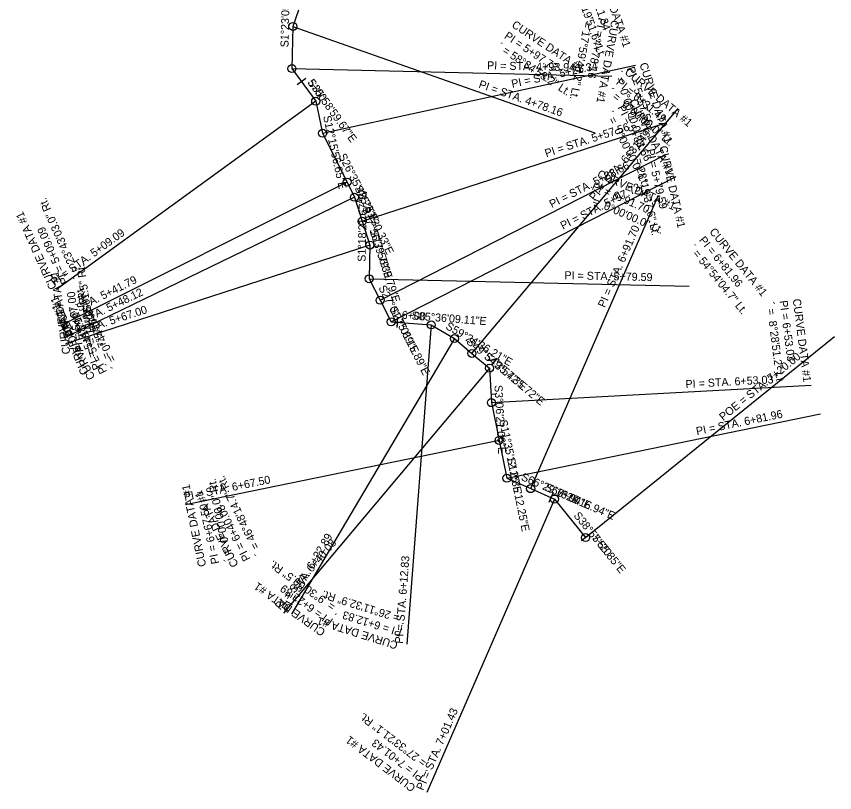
# Model space of a CAD drawing. Extents: x 1158784 to 1165006, y 610007 to 611539.
# Drawn here: x 1162821.2 to 1163128, y 610196.9 to 610487.8 of the extents above; entities that cross this region are included whole.
import ezdxf

# ---------------------------------------------------------------- set-up
doc = ezdxf.new("R2010")
doc.units = 0
for name, color, linetype in [('D_Roadway_Centerline', 7, 'Continuous'), ('D_Roadway_Centerline_Bearings', 7, 'Continuous'), ('D_Roadway_Centerline_CurveData', 7, 'Continuous'), ('D_Roadway_Centerline_Flags', 7, 'Continuous'), ('D_Roadway_Centerline_Text', 7, 'Continuous')]:
    doc.layers.add(name, color=color, linetype=linetype)

msp = doc.modelspace()

# ---------------------------------------------------------------- linework, layer by layer
at = {"layer": 'D_Roadway_Centerline'}
for p, q in [((1162927.06, 610490.12), (1162924.92, 610484.02)), ((1162924.92, 610484.02), (1162924.53, 610468.24)), ((1162924.53, 610468.24), (1162933.44, 610455.98)), ((1162933.44, 610455.98), (1162936.04, 610444.01)), ((1162936.04, 610444.01), (1162945.2, 610425.72)), ((1162945.2, 610425.72), (1162947.96, 610420.03)), ((1162947.96, 610420.03), (1162950.87, 610411.05)), ((1162950.87, 610411.05), (1162953.77, 610402.07)), ((1162953.77, 610402.07), (1162953.49, 610389.48)), ((1162953.49, 610389.48), (1162957.61, 610381.4)), ((1162957.61, 610381.4), (1162961.73, 610373.32)), ((1162961.73, 610373.32), (1162976.78, 610372.16)), ((1162976.78, 610372.16), (1162985.44, 610367.04)), ((1162985.44, 610367.04), (1162992.02, 610361.5)), ((1162992.02, 610361.5), (1162998.6, 610355.97)), ((1162998.6, 610355.97), (1162999.3, 610343.04)), ((1162999.3, 610343.04), (1163002.2, 610328.87)), ((1163002.2, 610328.87), (1163005.11, 610314.7)), ((1163005.11, 610314.7), (1163014.03, 610310.81)), ((1163014.03, 610310.81), (1163022.96, 610306.93)), ((1163022.96, 610306.93), (1163034.63, 610292.48))]:
    msp.add_line(p, q, dxfattribs=at)
at = {"layer": 'D_Roadway_Centerline_Flags'}
for points in [[(1162924.92, 610484.02), (1163038.11, 610444.19)], [(1162936.04, 610444.01), (1163053.3, 610469.5)], [(1162924.53, 610468.24), (1163044.5, 610465.34)], [(1162933.44, 610455.98), (1162836.34, 610385.47)], [(1162992.02, 610361.5), (1163069.3, 610453.31)], [(1162950.87, 610411.05), (1163065.03, 610448.02)], [(1162957.61, 610381.4), (1163064.51, 610435.92)], [(1162945.2, 610425.72), (1162837.9, 610372)], [(1162961.73, 610373.32), (1163068.63, 610427.84)], [(1162947.96, 610420.03), (1162839.97, 610367.69)], [(1163014.03, 610310.81), (1163061.91, 610420.85)], [(1162953.77, 610402.07), (1162839.61, 610365.1)], [(1162953.49, 610389.48), (1163073.46, 610386.75)], [(1162976.78, 610372.16), (1162967.58, 610252.51)], [(1163034.63, 610292.48), (1163127.98, 610367.89)], [(1162985.44, 610367.04), (1162924.38, 610263.74)], [(1162998.6, 610355.97), (1162921.32, 610264.16)], [(1162999.3, 610343.04), (1163119.12, 610349.54)], [(1163005.11, 610314.7), (1163122.66, 610338.8)], [(1163002.2, 610328.87), (1162884.65, 610304.76)], [(1163022.96, 610306.93), (1162975.09, 610196.89)]]:
    msp.add_lwpolyline(points, dxfattribs=at)
for centre in [(1162924.92, 610484.02), (1162924.53, 610468.24), (1162933.44, 610455.98), (1162936.04, 610444.01), (1162945.2, 610425.72), (1162947.96, 610420.03), (1162950.87, 610411.05), (1162953.77, 610402.07), (1162953.49, 610389.48), (1162957.61, 610381.4), (1162961.73, 610373.32), (1162976.78, 610372.16), (1162985.44, 610367.04), (1162992.02, 610361.5), (1162998.6, 610355.97), (1162999.3, 610343.04), (1163002.2, 610328.87), (1163005.11, 610314.7), (1163014.03, 610310.81), (1163022.96, 610306.93), (1163034.63, 610292.48)]:
    msp.add_circle(centre, 1.5, dxfattribs=at)
at = {"layer": 'D_Roadway_Centerline_Text'}
for points in [[(1162929.72, 610464.51), (1162926.48, 610462.16)], [(1162950.44, 610418.86), (1162948.54, 610418.24)], [(1162964.15, 610375.14), (1162963.84, 610371.15)], [(1163001.13, 610346.17), (1162999.13, 610346.06)], [(1163022.45, 610309.33), (1163020.85, 610305.67)], [(1163036.18, 610293.74), (1163033.07, 610291.23)], [(1163036.18, 610293.74), (1163033.07, 610291.23)]]:
    msp.add_lwpolyline(points, dxfattribs=at)

# ---------------------------------------------------------------- texts
at = {"layer": 'D_Roadway_Centerline_Bearings'}
for s, rotation, p in [('S1%%d23\'05.95"W', 88.615, (1162923.23, 610476.17)), ('S35%%d58\'59.67"E', 305.9832, (1162930.2, 610462.99)), ('S12%%d15\'56.65"E', 282.2657, (1162936.21, 610450.31)), ('S26%%d35\'48.23"E', 296.5967, (1162941.96, 610435.54)), ('S25%%d51\'30.33"E', 295.8584, (1162947.93, 610423.53)), ('S1%%d18\'21.67"W', 88.694, (1162952.13, 610395.81)), ('S17%%d56\'39.79"E', 287.9444, (1162950.84, 610416)), ('S17%%d56\'39.79"E', 287.9444, (1162953.75, 610407.02)), ('S27%%d01\'15.89"E', 297.0211, (1162956.88, 610386.12)), ('S27%%d01\'15.89"E', 297.0211, (1162961.01, 610378.04)), ('S85%%d36\'09.11"E', 355.6025, (1162969.37, 610374.23)), ('S59%%d24\'36.21"E', 329.4101, (1162981.88, 610370.89)), ('S49%%d54\'35.72"E', 319.9099, (1162989.7, 610365.42)), ('S49%%d54\'35.72"E', 319.9099, (1162996.28, 610359.88)), ('S3%%d06\'21.06"E', 273.1059, (1163000.45, 610349.58)), ('S11%%d35\'12.25"E', 281.5867, (1163002.22, 610336.25)), ('S11%%d35\'12.25"E', 281.5867, (1163005.13, 610322.08)), ('S66%%d29\'16.94"E', 336.488, (1163010.17, 610314.13)), ('S66%%d29\'16.94"E', 336.488, (1163019.09, 610310.25)), ('S38%%d55\'55.85"E', 308.9322, (1163029.96, 610300.65))]:
    msp.add_text(s, height=3, rotation=rotation, dxfattribs=at).set_placement(p)
at = {"layer": 'D_Roadway_Centerline_CurveData'}
for s, rotation, p in [('CURVE DATA #1', 289.4312, (1163038.39, 610505.56)), ('´ = 14%%d19\'51.6" Lt.', 289.4312, (1163028.96, 610502.24)), ('PI = 5+21.34', 289.4312, (1163033.68, 610503.9)), ('´ = 17%%d59\'48.2" Lt.', 259.6166, (1163034.49, 610488.34)), ('PI = 4+78.16', 259.6166, (1163039.41, 610487.44)), ('CURVE DATA #1', 326.3118, (1163006.66, 610483.98)), ('CURVE DATA #1', 259.6166, (1163044.32, 610486.54)), ('PI = 5+97.73', 326.3118, (1163003.88, 610479.82)), ('´ = 58%%d34\'53.2" Lt.', 326.3118, (1163001.11, 610475.66)), ('PI = 5+57.56', 287.9444, (1163050.02, 610468.39)), ('CURVE DATA #1', 287.9444, (1163054.78, 610469.93)), ('´ =  0%%d00\'00.0" Lt.', 287.9444, (1163045.27, 610466.85)), ('CURVE DATA #1', 319.9099, (1163049.01, 610466.47)), ('PI = 6+31.49', 319.9099, (1163045.79, 610462.64)), ('´ =  0%%d00\'00.0" Lt.', 319.9099, (1163042.57, 610458.82)), ('CURVE DATA #1', 297.0211, (1163050.93, 610455.94)), ('PI = 5+88.66', 297.0211, (1163046.48, 610453.66)), ('´ =  0%%d00\'00.0" Lt.', 297.0211, (1163042.03, 610451.39)), ('PI = 5+79.59', 282.8575, (1163057.34, 610437.8)), ('CURVE DATA #1', 282.8575, (1163062.21, 610438.92)), ('´ = 28%%d19\'37.6" Lt.', 282.8575, (1163052.46, 610436.69)), ('CURVE DATA #1', 336.488, (1163038.7, 610427.67)), ('PI = 6+91.70', 336.488, (1163036.71, 610423.09)), ('´ = 23%%d43\'03.0" Rt.', 114.1245, (1162845.6, 610390.34)), ('´ =  0%%d00\'00.0" Lt.', 336.488, (1163034.71, 610418.5)), ('CURVE DATA #1', 114.1245, (1162836.47, 610386.25)), ('PI = 5+09.09', 114.1245, (1162841.03, 610388.3)), ('CURVE DATA #1', 309.0374, (1163080.87, 610407.03)), ('PI = 6+81.96', 309.0374, (1163076.99, 610403.88)), ('´ = 54%%d54\'04.7" Lt.', 309.0374, (1163073.1, 610400.73)), ('´ = 19%%d15\'01.5" Rt.', 98.3192, (1162851.37, 610362.84)), ('CURVE DATA #1', 98.3192, (1162841.48, 610361.39)), ('´ =  7%%d54\'50.5" Rt.', 111.9014, (1162857.63, 610357.85)), ('CURVE DATA #1', 111.9014, (1162848.35, 610354.12)), ('PI = 5+67.00', 98.3192, (1162846.43, 610362.12)), ('´ =  0%%d44\'17.9" Rt.', 116.2276, (1162859.82, 610356.91)), ('CURVE DATA #1', 116.2276, (1162850.85, 610352.49)), ('´ =  8%%d28\'51.2" Lt.', 277.3463, (1163102.35, 610380.52)), ('PI = 6+53.03', 277.3463, (1163107.31, 610381.16)), ('CURVE DATA #1', 277.3463, (1163112.27, 610381.8)), ('PI = 5+48.12', 111.9014, (1162852.99, 610355.98)), ('PI = 5+41.79', 116.2276, (1162855.34, 610354.7)), ('´ = 46%%d48\'14.7" Rt.', 116.5079, (1162913.56, 610286.73)), ('CURVE DATA #1', 101.5867, (1162892.41, 610281.86)), ('´ =  0%%d00\'00.0" Rt.', 101.5867, (1162902.21, 610283.87)), ('CURVE DATA #1', 116.5079, (1162904.61, 610282.27)), ('PI = 6+67.50', 101.5867, (1162897.31, 610282.86)), ('PI = 6+40.08', 116.5079, (1162909.08, 610284.5)), ('´ =  9%%d30\'00.5" Rt.', 144.66, (1162943.13, 610265.87)), ('CURVE DATA #1', 144.66, (1162937.35, 610257.72)), ('PI = 6+22.89', 144.66, (1162940.24, 610261.79)), ('´ = 26%%d11\'32.9" Rt.', 162.5063, (1162967.51, 610262.89)), ('PI = 6+12.83', 162.5063, (1162966, 610258.13)), ('CURVE DATA #1', 162.5063, (1162964.5, 610253.36)), ('´ = 27%%d33\'21.1" Rt.', 142.7101, (1162977.23, 610207.26)), ('CURVE DATA #1', 142.7101, (1162971.17, 610199.31)), ('PI = 7+01.43', 142.7101, (1162974.2, 610203.28))]:
    msp.add_text(s, height=3, rotation=rotation, dxfattribs=at).set_placement(p)
at = {"layer": 'D_Roadway_Centerline_Flags'}
for s, rotation, p in [('PI = STA. 4+93.94', 358.615, (1162997.65, 610467.98)), ('PI = STA. 5+21.34', 12.2657, (1163007.15, 610461)), ('PI = STA. 4+78.16', 340.6183, (1162994.31, 610461.19)), ('PI = STA. 5+57.56', 17.9444, (1163019.89, 610434.98)), ('PI = STA. 6+31.49', 49.9099, (1163037.99, 610418.44)), ('PI = STA. 5+88.66', 27.0211, (1163021.99, 610415.92)), ('PI = STA. 5+97.73', 27.0211, (1163026.11, 610407.83)), ('PI = STA. 5+09.09', 35.9832, (1162835.46, 610386.68)), ('PI = STA. 6+91.70', 66.488, (1163041.82, 610378.44)), ('PI = STA. 5+79.59', 358.694, (1163026.67, 610389.32)), ('PI = STA. 5+41.79', 26.5967, (1162837.23, 610373.34)), ('PI = STA. 5+48.12', 25.8584, (1162839.32, 610369.04)), ('PI = STA. 5+67.00', 17.9444, (1162839.15, 610366.53)), ('POE = STA. 7+20.00', 38.9322, (1163086.2, 610336.08)), ('PI = STA. 6+53.03', 3.1059, (1163072.15, 610348.49)), ('PI = STA. 6+81.96', 11.5867, (1163076.36, 610330.83)), ('PI = STA. 6+67.50', 11.5867, (1162884.35, 610306.23)), ('PI = STA. 6+22.89', 59.4101, (1162923.09, 610264.5)), ('PI = STA. 6+40.08', 49.9099, (1162920.17, 610265.13)), ('PI = STA. 6+12.83', 85.6025, (1162966.08, 610252.63)), ('PI = STA. 7+01.43', 66.488, (1162973.71, 610197.49))]:
    msp.add_text(s, height=3, rotation=rotation, dxfattribs=at).set_placement(p)
at = {"layer": 'D_Roadway_Centerline_Text'}
for s, rotation, p in [('5+00', 305.9832, (1162930.19, 610463)), ('6+00', 355.6025, (1162965.6, 610374.52)), ('7+00', 336.488, (1163023.62, 610308.28)), ('7+20', 308.9322, (1163036.74, 610292.26)), ('7+20', 308.9322, (1163036.74, 610292.26))]:
    msp.add_text(s, height=3, rotation=rotation, dxfattribs=at).set_placement(p)

doc.saveas('drawing.dxf')
